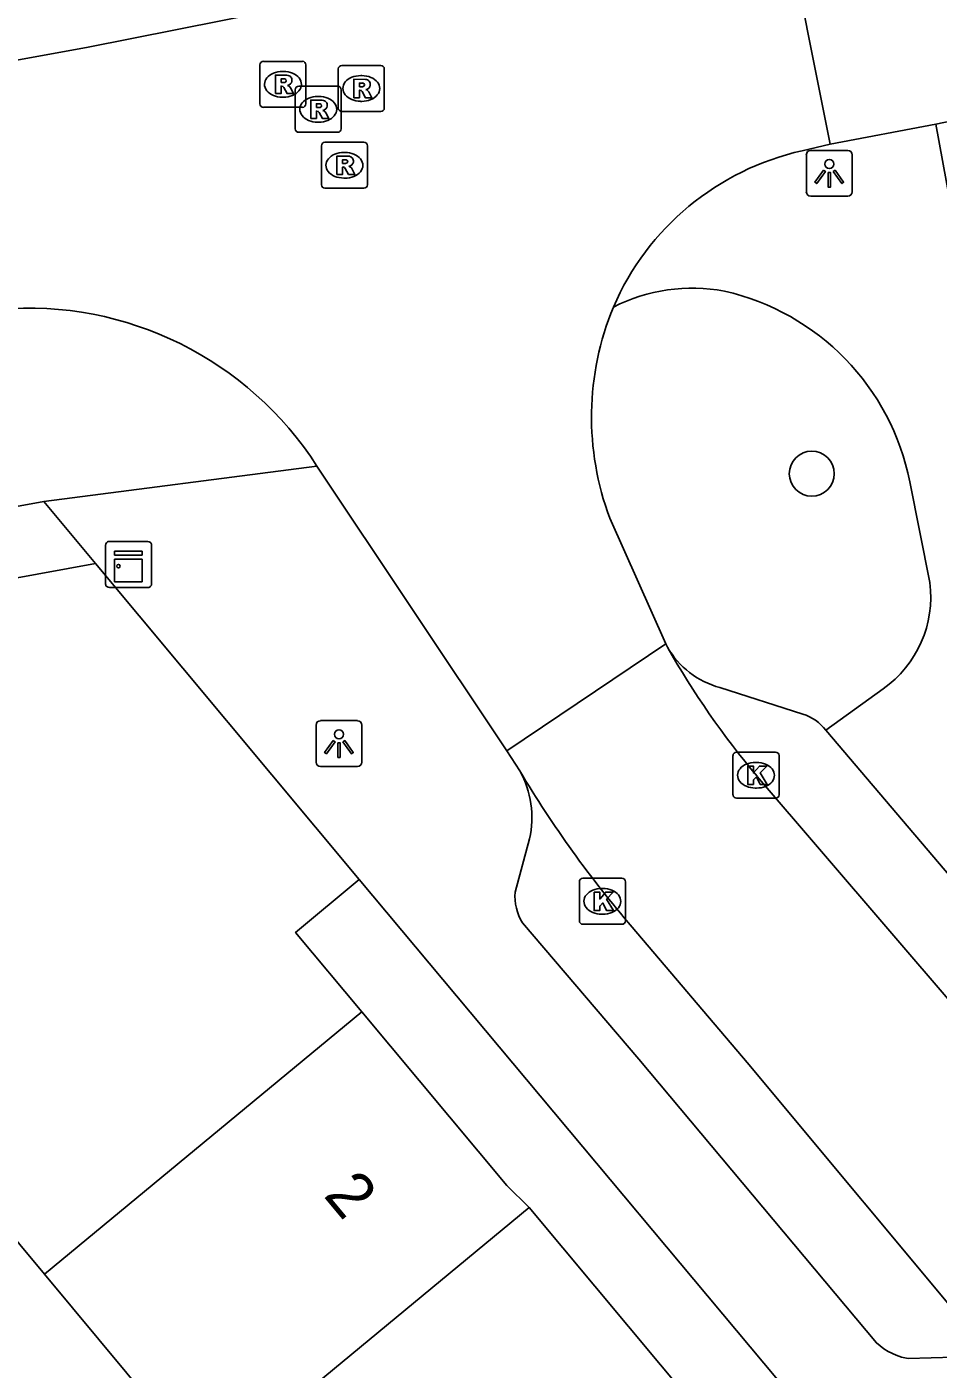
# Model space of a CAD drawing. Extents: x 160379 to 161131, y 383940 to 384849.
# Drawn here: x 160747.99 to 160767.81, y 384486.99 to 384516.19 of the extents above; entities that cross this region are included whole.
import ezdxf

# ---------------------------------------------------------------- set-up
doc = ezdxf.new("R2010")
doc.units = 0
for name, color, linetype in [('IMGEO_Boom', 7, 'Continuous'), ('IMGEO_Kast', 7, 'Continuous'), ('IMGEO_Kolk', 7, 'Continuous'), ('IMGEO_Lichtpunt', 7, 'Continuous'), ('IMGEO_Pand', 7, 'Continuous'), ('IMGEO_Pand_nummerreeks', 7, 'Continuous'), ('IMGEO_Parkeervlak_open', 7, 'Continuous'), ('IMGEO_Rijbaan_lokaal_open', 7, 'Continuous'), ('IMGEO_Rioolput', 7, 'Continuous'), ('IMGEO_Voetpad_open', 7, 'Continuous')]:
    doc.layers.add(name, color=color, linetype=linetype)

msp = doc.modelspace()

# ---------------------------------------------------------------- linework, layer by layer
at = {"layer": 'IMGEO_Boom'}
msp.add_circle((160765.063, 384506.469), 0.489, dxfattribs=at)
at = {"layer": 'IMGEO_Kast'}
for p, q in [((160749.699, 384504.068), (160749.699, 384504.909)), ((160749.699, 384504.909), (160749.699, 384504.068)), ((160749.774, 384504.993), (160750.615, 384504.993)), ((160750.615, 384504.993), (160749.774, 384504.993)), ((160750.699, 384504.918), (160750.699, 384504.077)), ((160750.699, 384504.077), (160750.699, 384504.918)), ((160750.624, 384503.993), (160749.783, 384503.993)), ((160749.783, 384503.993), (160750.624, 384503.993))]:
    msp.add_line(p, q, dxfattribs=at)
for points in [[(160749.894, 384504.783), (160750.494, 384504.783), (160750.494, 384504.698), (160749.894, 384504.698), (160749.894, 384504.783)], [(160749.894, 384504.608), (160750.494, 384504.608), (160750.494, 384504.119), (160749.894, 384504.119), (160749.894, 384504.608)]]:
    msp.add_lwpolyline(points, dxfattribs=at)
msp.add_circle((160749.978, 384504.457), 0.0377, dxfattribs=at)
for centre, start, end in [((160749.777, 384504.915), 92.4484, 184.2845), ((160749.777, 384504.915), 92.4484, 184.2845), ((160750.621, 384504.915), 2.4484, 94.2845), ((160750.621, 384504.915), 2.4484, 94.2845), ((160749.777, 384504.071), 182.4484, 274.2845), ((160749.777, 384504.071), 182.4484, 274.2845), ((160750.621, 384504.071), 272.4484, 4.2845), ((160750.621, 384504.071), 272.4484, 4.2845)]:
    msp.add_arc(centre, 0.0779, start, end, dxfattribs=at)
at = {"layer": 'IMGEO_Kolk'}
for p, q in [((160763.424, 384500.41), (160764.276, 384500.41)), ((160763.349, 384499.484), (160763.349, 384500.336)), ((160763.837, 384500.19), (160763.862, 384500.19)), ((160764.35, 384500.336), (160764.35, 384499.484)), ((160763.86, 384499.63), (160763.835, 384499.63)), ((160764.276, 384499.41), (160763.424, 384499.41)), ((160760.006, 384496.742), (160760.006, 384497.594)), ((160760.081, 384497.668), (160760.933, 384497.668)), ((160760.494, 384497.448), (160760.519, 384497.448)), ((160761.007, 384497.594), (160761.007, 384496.742)), ((160760.517, 384496.888), (160760.492, 384496.888)), ((160760.933, 384496.668), (160760.081, 384496.668))]:
    msp.add_line(p, q, dxfattribs=at)
for points in [[(160763.424, 384500.41), (160764.276, 384500.41)], [(160763.349, 384499.484), (160763.349, 384500.336)], [(160763.67, 384500.11), (160763.793, 384500.11), (160763.793, 384499.959), (160763.923, 384500.11), (160764.087, 384500.11), (160763.941, 384499.959), (160764.094, 384499.71), (160763.942, 384499.71), (160763.857, 384499.874), (160763.793, 384499.807), (160763.793, 384499.71), (160763.67, 384499.71), (160763.67, 384500.11)], [(160764.35, 384500.336), (160764.35, 384499.484)], [(160764.276, 384499.41), (160763.424, 384499.41)], [(160760.006, 384496.742), (160760.006, 384497.594)], [(160760.081, 384497.668), (160760.933, 384497.668)], [(160761.007, 384497.594), (160761.007, 384496.742)], [(160760.327, 384497.368), (160760.45, 384497.368), (160760.45, 384497.217), (160760.58, 384497.368), (160760.744, 384497.368), (160760.598, 384497.217), (160760.751, 384496.968), (160760.599, 384496.968), (160760.514, 384497.132), (160760.45, 384497.065), (160760.45, 384496.968), (160760.327, 384496.968), (160760.327, 384497.368)], [(160760.933, 384496.668), (160760.081, 384496.668)]]:
    msp.add_lwpolyline(points, dxfattribs=at)
for centre, start, end in [((160763.426, 384500.334), 91.552, 178.448), ((160763.426, 384500.334), 91.552, 178.448), ((160764.274, 384500.334), 1.552, 88.448), ((160764.274, 384500.334), 1.552, 88.448), ((160763.426, 384499.486), 181.552, 268.448), ((160763.426, 384499.486), 181.552, 268.448), ((160764.274, 384499.486), 271.552, 358.448), ((160764.274, 384499.486), 271.552, 358.448), ((160760.083, 384497.592), 91.552, 178.448), ((160760.083, 384497.592), 91.552, 178.448), ((160760.931, 384497.592), 1.552, 88.448), ((160760.931, 384497.592), 1.552, 88.448), ((160760.083, 384496.744), 181.552, 268.448), ((160760.083, 384496.744), 181.552, 268.448), ((160760.931, 384496.744), 271.552, 358.448), ((160760.931, 384496.744), 271.552, 358.448)]:
    msp.add_arc(centre, 0.0765, start, end, dxfattribs=at)
for centre, major_axis, ratio, start_param, end_param in [((160763.836, 384499.91), (-0.387, 0.002), 0.722429, 4.712389, 7.853982), ((160763.861, 384499.91), (-0.39, 0.002), 0.717154, 1.570796, 4.712389), ((160760.493, 384497.168), (-0.387, 0.002), 0.722429, 4.712389, 7.853982), ((160760.518, 384497.168), (-0.39, 0.002), 0.717154, 1.570796, 4.712389)]:
    msp.add_ellipse(centre, major_axis=major_axis, ratio=ratio, start_param=start_param, end_param=end_param, dxfattribs=at)
at = {"layer": 'IMGEO_Lichtpunt'}
for p, q in [((160765.847, 384513.501), (160765.039, 384513.501)), ((160765.847, 384513.501), (160765.039, 384513.501)), ((160764.945, 384513.406), (160764.945, 384512.599)), ((160764.945, 384513.406), (160764.945, 384512.599)), ((160765.941, 384512.599), (160765.941, 384513.406)), ((160765.941, 384512.599), (160765.941, 384513.406)), ((160765.039, 384512.505), (160765.847, 384512.505)), ((160765.039, 384512.505), (160765.847, 384512.505)), ((160754.278, 384501.002), (160754.278, 384500.195)), ((160754.278, 384501.002), (160754.278, 384500.195)), ((160755.18, 384501.097), (160754.372, 384501.097)), ((160755.18, 384501.097), (160754.372, 384501.097)), ((160755.274, 384500.195), (160755.274, 384501.002)), ((160755.274, 384500.195), (160755.274, 384501.002)), ((160754.372, 384500.101), (160755.18, 384500.101)), ((160754.372, 384500.101), (160755.18, 384500.101))]:
    msp.add_line(p, q, dxfattribs=at)
for points in [[(160765.319, 384513.07), (160765.358, 384513.042), (160765.17, 384512.78), (160765.132, 384512.807), (160765.319, 384513.07)], [(160765.421, 384513.022), (160765.468, 384513.022), (160765.468, 384512.7), (160765.421, 384512.7), (160765.421, 384513.022)], [(160765.531, 384513.042), (160765.569, 384513.069), (160765.756, 384512.807), (160765.717, 384512.779), (160765.531, 384513.042)], [(160754.652, 384500.666), (160754.691, 384500.638), (160754.503, 384500.376), (160754.465, 384500.403), (160754.652, 384500.666)], [(160754.864, 384500.638), (160754.902, 384500.665), (160755.089, 384500.403), (160755.05, 384500.375), (160754.864, 384500.638)], [(160754.754, 384500.618), (160754.801, 384500.618), (160754.801, 384500.296), (160754.754, 384500.296), (160754.754, 384500.618)]]:
    msp.add_lwpolyline(points, dxfattribs=at)
for centre in [(160765.444, 384513.204), (160754.777, 384500.8)]:
    msp.add_circle(centre, 0.0994, dxfattribs=at)
for centre, start, end in [((160765.039, 384513.406), 90, 180), ((160765.039, 384513.406), 90, 180), ((160765.847, 384513.406), 0, 90), ((160765.847, 384513.406), 0, 90), ((160765.039, 384512.599), 180, 270), ((160765.039, 384512.599), 180, 270), ((160765.847, 384512.599), 270, 0), ((160765.847, 384512.599), 270, 360), ((160754.372, 384501.002), 90, 180), ((160754.372, 384501.002), 90, 180), ((160755.18, 384501.002), 0, 90), ((160755.18, 384501.002), 0, 90), ((160754.372, 384500.195), 180, 270), ((160754.372, 384500.195), 180, 270), ((160755.18, 384500.195), 270, 0), ((160755.18, 384500.195), 270, 360)]:
    msp.add_arc(centre, 0.0946, start, end, dxfattribs=at)
at = {"layer": 'IMGEO_Pand'}
for points in [[(160749.48, 384504.514), (160747.616, 384504.174), (160747.441, 384504.142), (160744.111, 384503.532), (160743.969, 384503.506), (160733.41, 384501.572)], [(160749.48, 384504.514), (160755.214, 384497.645)], [(160755.275, 384494.766), (160753.833, 384496.492), (160755.214, 384497.645)], [(160748.367, 384489.058), (160755.275, 384494.766)], [(160758.913, 384490.507), (160758.429, 384490.99), (160755.275, 384494.766)], [(160748.367, 384489.058), (160744.603, 384493.576), (160735.181, 384491.847)], [(160751.951, 384484.755), (160758.913, 384490.507)], [(160762.505, 384486.211), (160758.913, 384490.507)], [(160751.951, 384484.755), (160748.367, 384489.058)]]:
    msp.add_lwpolyline(points, dxfattribs=at)
at = {"layer": 'IMGEO_Parkeervlak_open'}
msp.add_lwpolyline([(160764.865, 384501.24), (160763.063, 384501.815)], dxfattribs=at)
for centre, radius, start, end in [((160763.569, 384503.65), 1.903, 210.0454, 254.5947), ((160764.59, 384500.316), 0.964, 36.3911, 73.4256)]:
    msp.add_arc(centre, radius, start, end, dxfattribs=at)
at = {"layer": 'IMGEO_Rijbaan_lokaal_open'}
for points in [[(160764.445, 384518.726), (160765.465, 384513.637)], [(160754.212, 384516.716), (160749.281, 384515.741), (160745.402, 384515.035)], [(160767.765, 384514.068), (160769.917, 384514.517)], [(160767.765, 384514.068), (160765.465, 384513.637)], [(160765.465, 384513.637), (160764.851, 384513.492)], [(160758.427, 384500.442), (160754.298, 384506.633)], [(160761.886, 384502.765), (160760.669, 384505.499)], [(160758.427, 384500.442), (160761.886, 384502.765)], [(160761.886, 384502.765), (160761.921, 384502.697)], [(160758.708, 384500.007), (160758.427, 384500.442)], [(160763.877, 384499.886), (160769.607, 384493.204), (160772.129, 384490.165), (160784.563, 384475.193), (160788.775, 384470.215)], [(160803.39, 384446.147), (160800.426, 384449.782), (160793.188, 384458.339), (160781.229, 384472.652), (160768.71, 384487.604), (160763.66, 384493.663), (160761.152, 384496.606)]]:
    msp.add_lwpolyline(points, dxfattribs=at)
for centre, radius, start, end in [((160766.135, 384507.763), 5.871, 102.6339, 156.6166), ((160748.005, 384502.594), 7.478, 32.6927, 94.6763), ((160766.545, 384507.698), 6.274, 157.5594, 200.5201), ((160778.112, 384511.878), 18.613, 209.5534, 220.11), ((160780.054, 384512.768), 24.869, 210.8714, 220.5316)]:
    msp.add_arc(centre, radius, start, end, dxfattribs=at)
at = {"layer": 'IMGEO_Rioolput'}
for p, q in [((160753.057, 384514.511), (160753.057, 384515.363)), ((160753.132, 384515.437), (160753.984, 384515.437)), ((160754.058, 384515.363), (160754.058, 384514.511)), ((160754.762, 384514.421), (160754.762, 384515.273)), ((160754.837, 384515.347), (160755.689, 384515.347)), ((160755.763, 384515.273), (160755.763, 384514.421)), ((160753.545, 384515.217), (160753.57, 384515.217)), ((160755.25, 384515.127), (160755.275, 384515.127)), ((160753.568, 384514.657), (160753.543, 384514.657)), ((160753.825, 384513.968), (160753.825, 384514.82)), ((160753.9, 384514.894), (160754.752, 384514.894)), ((160754.313, 384514.674), (160754.338, 384514.674)), ((160754.826, 384514.82), (160754.826, 384513.968)), ((160753.984, 384514.437), (160753.132, 384514.437)), ((160755.273, 384514.567), (160755.248, 384514.567)), ((160754.336, 384514.114), (160754.311, 384514.114)), ((160755.689, 384514.347), (160754.837, 384514.347)), ((160754.752, 384513.894), (160753.9, 384513.894)), ((160754.394, 384512.751), (160754.394, 384513.603)), ((160754.469, 384513.677), (160755.321, 384513.677)), ((160755.395, 384513.603), (160755.395, 384512.751)), ((160754.882, 384513.457), (160754.907, 384513.457)), ((160754.905, 384512.897), (160754.88, 384512.897)), ((160755.321, 384512.677), (160754.469, 384512.677))]:
    msp.add_line(p, q, dxfattribs=at)
for points in [[(160753.057, 384514.511), (160753.057, 384515.363)], [(160753.132, 384515.437), (160753.984, 384515.437)], [(160754.058, 384515.363), (160754.058, 384514.511)], [(160754.762, 384514.421), (160754.762, 384515.273)], [(160754.837, 384515.347), (160755.689, 384515.347)], [(160755.763, 384515.273), (160755.763, 384514.421)], [(160753.646, 384515.135), (160753.394, 384515.137), (160753.394, 384514.737)], [(160753.572, 384515.056), (160753.518, 384515.056), (160753.518, 384514.975)], [(160753.518, 384514.975), (160753.57, 384514.975)], [(160755.351, 384515.045), (160755.099, 384515.047), (160755.099, 384514.647)], [(160755.277, 384514.966), (160755.223, 384514.966), (160755.223, 384514.885)], [(160753.394, 384514.737), (160753.518, 384514.737), (160753.518, 384514.899), (160753.529, 384514.899)], [(160753.576, 384514.87), (160753.647, 384514.737), (160753.787, 384514.737), (160753.722, 384514.863)], [(160753.825, 384513.968), (160753.825, 384514.82)], [(160753.9, 384514.894), (160754.752, 384514.894)], [(160754.826, 384514.82), (160754.826, 384513.968)], [(160755.099, 384514.647), (160755.223, 384514.647), (160755.223, 384514.809), (160755.234, 384514.809)], [(160755.223, 384514.885), (160755.275, 384514.885)], [(160755.281, 384514.78), (160755.352, 384514.647), (160755.492, 384514.647), (160755.427, 384514.773)], [(160753.984, 384514.437), (160753.132, 384514.437)], [(160754.414, 384514.592), (160754.162, 384514.594), (160754.162, 384514.194)], [(160754.162, 384514.194), (160754.286, 384514.194), (160754.286, 384514.356), (160754.297, 384514.356)], [(160754.34, 384514.513), (160754.286, 384514.513), (160754.286, 384514.432)], [(160754.286, 384514.432), (160754.338, 384514.432)], [(160754.344, 384514.327), (160754.415, 384514.194), (160754.555, 384514.194), (160754.49, 384514.32)], [(160755.689, 384514.347), (160754.837, 384514.347)], [(160754.752, 384513.894), (160753.9, 384513.894)], [(160754.394, 384512.751), (160754.394, 384513.603)], [(160754.469, 384513.677), (160755.321, 384513.677)], [(160755.395, 384513.603), (160755.395, 384512.751)], [(160754.983, 384513.375), (160754.731, 384513.377), (160754.731, 384512.977)], [(160754.909, 384513.296), (160754.855, 384513.296), (160754.855, 384513.215)], [(160754.855, 384513.215), (160754.907, 384513.215)], [(160754.731, 384512.977), (160754.855, 384512.977), (160754.855, 384513.139), (160754.866, 384513.139)], [(160754.913, 384513.11), (160754.984, 384512.977), (160755.124, 384512.977), (160755.059, 384513.103)], [(160755.321, 384512.677), (160754.469, 384512.677)]]:
    msp.add_lwpolyline(points, dxfattribs=at)
for centre, radius, start, end in [((160753.134, 384515.361), 0.0765, 91.552, 178.448), ((160753.134, 384515.361), 0.0765, 91.552, 178.448), ((160753.982, 384515.361), 0.0765, 1.552, 88.448), ((160753.982, 384515.361), 0.0765, 1.552, 88.448), ((160754.839, 384515.271), 0.0765, 91.552, 178.448), ((160754.839, 384515.271), 0.0765, 91.552, 178.448), ((160755.687, 384515.271), 0.0765, 1.552, 88.448), ((160755.687, 384515.271), 0.0765, 1.552, 88.448), ((160753.554, 384515.164), 0.19, 274.7715, 282.9687), ((160753.578, 384514.96), 0.0964, 77.0061, 93.1865), ((160753.592, 384515.017), 0.0378, 276.6634, 79.6772), ((160753.645, 384515.025), 0.109, 350.3612, 89.416), ((160753.643, 384515.025), 0.112, 277.5842, 350.9817), ((160755.283, 384514.87), 0.0964, 77.0061, 93.1865), ((160755.297, 384514.927), 0.0378, 276.6634, 79.6772), ((160755.35, 384514.935), 0.109, 350.3612, 89.416), ((160753.528, 384514.846), 0.0533, 26.0293, 88.6989), ((160753.627, 384514.81), 0.108, 29.5134, 73.7905), ((160753.902, 384514.818), 0.0765, 91.552, 178.448), ((160753.902, 384514.818), 0.0765, 91.552, 178.448), ((160754.75, 384514.818), 0.0765, 1.552, 88.448), ((160754.75, 384514.818), 0.0765, 1.552, 88.448), ((160755.233, 384514.756), 0.0533, 26.0293, 88.6989), ((160755.259, 384515.074), 0.19, 274.7715, 282.9687), ((160755.348, 384514.935), 0.112, 277.5842, 350.9817), ((160755.332, 384514.72), 0.108, 29.5134, 73.7905), ((160753.134, 384514.513), 0.0765, 181.552, 268.448), ((160753.134, 384514.513), 0.0765, 181.552, 268.448), ((160753.982, 384514.513), 0.0765, 271.552, 358.448), ((160753.982, 384514.513), 0.0765, 271.552, 358.448), ((160754.296, 384514.303), 0.0533, 26.0293, 88.6989), ((160754.322, 384514.621), 0.19, 274.7715, 282.9687), ((160754.346, 384514.417), 0.0964, 77.0061, 93.1865), ((160754.36, 384514.474), 0.0378, 276.6634, 79.6772), ((160754.413, 384514.482), 0.109, 350.3612, 89.416), ((160754.411, 384514.482), 0.112, 277.5842, 350.9817), ((160754.395, 384514.267), 0.108, 29.5134, 73.7905), ((160754.839, 384514.423), 0.0765, 181.552, 268.448), ((160754.839, 384514.423), 0.0765, 181.552, 268.448), ((160755.687, 384514.423), 0.0765, 271.552, 358.448), ((160755.687, 384514.423), 0.0765, 271.552, 358.448), ((160753.902, 384513.97), 0.0765, 181.552, 268.448), ((160753.902, 384513.97), 0.0765, 181.552, 268.448), ((160754.75, 384513.97), 0.0765, 271.552, 358.448), ((160754.75, 384513.97), 0.0765, 271.552, 358.448), ((160754.471, 384513.601), 0.0765, 91.552, 178.448), ((160754.471, 384513.601), 0.0765, 91.552, 178.448), ((160755.319, 384513.601), 0.0765, 1.552, 88.448), ((160755.319, 384513.601), 0.0765, 1.552, 88.448), ((160754.891, 384513.404), 0.19, 274.7715, 282.9687), ((160754.915, 384513.2), 0.0964, 77.0061, 93.1865), ((160754.929, 384513.257), 0.0378, 276.6634, 79.6772), ((160754.982, 384513.265), 0.109, 350.3612, 89.416), ((160754.98, 384513.265), 0.112, 277.5842, 350.9817), ((160754.865, 384513.086), 0.0533, 26.0293, 88.6989), ((160754.964, 384513.05), 0.108, 29.5134, 73.7905), ((160754.471, 384512.753), 0.0765, 181.552, 268.448), ((160754.471, 384512.753), 0.0765, 181.552, 268.448), ((160755.319, 384512.753), 0.0765, 271.552, 358.448), ((160755.319, 384512.753), 0.0765, 271.552, 358.448)]:
    msp.add_arc(centre, radius, start, end, dxfattribs=at)
for centre, major_axis, ratio, start_param, end_param in [((160753.544, 384514.937), (-0.387, 0.002), 0.722429, 4.712389, 7.853982), ((160753.569, 384514.937), (-0.39, 0.002), 0.717154, 1.570796, 4.712389), ((160755.249, 384514.847), (-0.387, 0.002), 0.722429, 4.712389, 7.853982), ((160755.274, 384514.847), (-0.39, 0.002), 0.717154, 1.570796, 4.712389), ((160754.312, 384514.394), (-0.387, 0.002), 0.722429, 4.712389, 7.853982), ((160754.337, 384514.394), (-0.39, 0.002), 0.717154, 1.570796, 4.712389), ((160754.881, 384513.177), (-0.387, 0.002), 0.722429, 4.712389, 7.853982), ((160754.906, 384513.177), (-0.39, 0.002), 0.717154, 1.570796, 4.712389)]:
    msp.add_ellipse(centre, major_axis=major_axis, ratio=ratio, start_param=start_param, end_param=end_param, dxfattribs=at)
at = {"layer": 'IMGEO_Voetpad_open'}
for points in [[(160768.147, 384511.974), (160767.765, 384514.068)], [(160754.298, 384506.633), (160748.356, 384505.867)], [(160767.195, 384506.293), (160767.629, 384504.1)], [(160702.23, 384497.471), (160748.356, 384505.867)], [(160748.356, 384505.867), (160749.48, 384504.514)], [(160766.613, 384501.788), (160765.366, 384500.888)], [(160765.366, 384500.888), (160771.302, 384493.916)], [(160758.607, 384497.368), (160758.922, 384498.527)], [(160755.214, 384497.645), (160796.819, 384447.928)], [(160768.164, 384487.256), (160767.163, 384487.224), (160767.016, 384487.252), (160766.897, 384487.294), (160766.722, 384487.378), (160766.631, 384487.431), (160766.471, 384487.564), (160761.303, 384493.732), (160758.77, 384496.698)]]:
    msp.add_lwpolyline(points, dxfattribs=at)
for centre, radius, start, end in [((160762.465, 384506.709), 3.796, 79.4287, 116.9245), ((160761.984, 384505.26), 5.312, 11.2141, 77.2032), ((160765.214, 384503.782), 2.436, 305.0591, 7.495), ((160756.907, 384498.991), 2.068, 347.0306, 29.4247), ((160759.771, 384497.296), 1.166, 176.4712, 210.8758)]:
    msp.add_arc(centre, radius, start, end, dxfattribs=at)

# ---------------------------------------------------------------- texts
at = {"layer": 'IMGEO_Pand_nummerreeks'}
msp.add_text('2', height=1, rotation=309.8973, dxfattribs=at).set_placement((160754.422, 384490.765))

doc.saveas('drawing.dxf')
